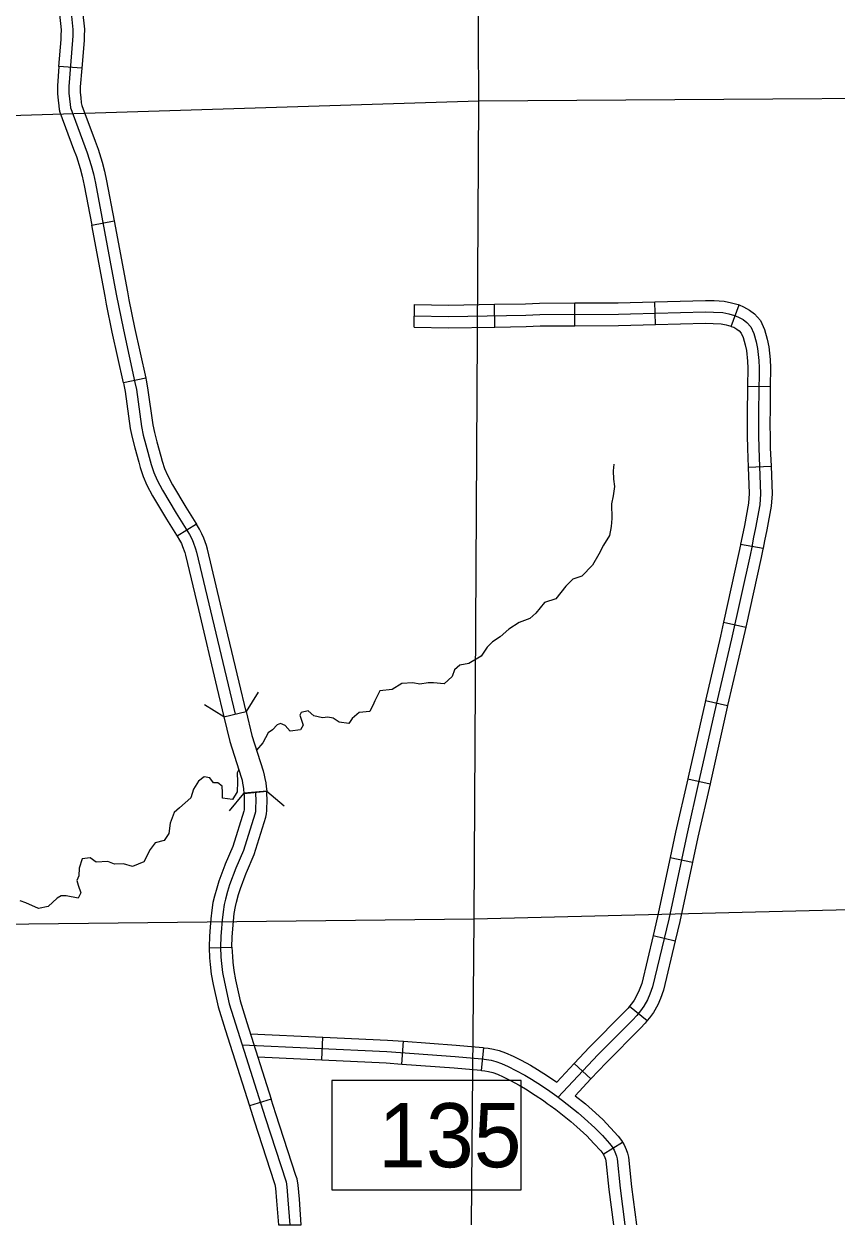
# Model space of a CAD drawing. Extents: x -492261 to -432772, y 1441225 to 1452922.
# Drawn here: x -458029.5 to -457876.9, y 1450742 to 1450967.5 of the extents above; entities that cross this region are included whole.
import ezdxf

# ---------------------------------------------------------------- set-up
doc = ezdxf.new("R2010")
doc.units = 0
doc.layers.add('Default', color=7, linetype='Continuous')

msp = doc.modelspace()

# ---------------------------------------------------------------- linework, layer by layer
at = {"layer": 'Default'}
for p, q in [((-458018.7, 1450959.21), (-458022.97, 1450959.56)), ((-458016.83, 1450929.76), (-458012.62, 1450930.54)), ((-458012.62, 1450930.54), (-458012.62, 1450930.54)), ((-457956.3, 1450910.57), (-457956.23, 1450914.86)), ((-457941.14, 1450910.61), (-457941.22, 1450914.89)), ((-457926.09, 1450910.86), (-457926.11, 1450915.15)), ((-457910.96, 1450911.08), (-457911.07, 1450915.37)), ((-457896.77, 1450910.75), (-457895.24, 1450914.76)), ((-458006.68, 1450901.04), (-458010.87, 1450900.11)), ((-457893.69, 1450899.49), (-457889.4, 1450899.43)), ((-457893.56, 1450884.3), (-457889.27, 1450884.46)), ((-457997.13, 1450873.6), (-458000.79, 1450871.36)), ((-457894.97, 1450869.82), (-457890.75, 1450869.06)), ((-457898.19, 1450855.17), (-457894.01, 1450854.24)), ((-457901.59, 1450840.5), (-457897.41, 1450839.52)), ((-457991.99, 1450837.4), (-457987.82, 1450838.39)), ((-457904.9, 1450825.77), (-457900.72, 1450824.82)), ((-457988.23, 1450823.04), (-457983.96, 1450823.45)), ((-457988.23, 1450823.06), (-457983.96, 1450823.44)), ((-457983.96, 1450823.44), (-457988.23, 1450823.06)), ((-457908.19, 1450811.02), (-457904, 1450810.12)), ((-457911.41, 1450796.33), (-457907.24, 1450795.34)), ((-457994.77, 1450794.02), (-457990.49, 1450794.18)), ((-457915.82, 1450783.06), (-457912.5, 1450780.35)), ((-457973.63, 1450772.97), (-457973.43, 1450777.25)), ((-457958.62, 1450772.2), (-457958.31, 1450776.48)), ((-457943.65, 1450771.01), (-457943.2, 1450775.27)), ((-457926.21, 1450772.33), (-457923.08, 1450769.4)), ((-457983.13, 1450765.63), (-457987.21, 1450764.33)), ((-457982.24, 1450762.82), (-457983.13, 1450765.63)), ((-457983.13, 1450765.63), (-457983.13, 1450765.63)), ((-457987.21, 1450764.33), (-457987.21, 1450764.33)), ((-457987.21, 1450764.33), (-457986.32, 1450761.51)), ((-457986.32, 1450761.51), (-457982.54, 1450749.97)), ((-457978.47, 1450751.3), (-457982.24, 1450762.82)), ((-457920.78, 1450755.28), (-457917.13, 1450757.52)), ((-457982.54, 1450749.97), (-457982.42, 1450749.58)), ((-457982.42, 1450749.58), (-457982.3, 1450748.88)), ((-457978.25, 1450750.62), (-457978.47, 1450751.3)), ((-457978.04, 1450749.43), (-457978.25, 1450750.62)), ((-457982.3, 1450748.88), (-457982.1, 1450746.5)), ((-457977.83, 1450746.83), (-457978.04, 1450749.43)), ((-457982.1, 1450746.5), (-457981.77, 1450741.98)), ((-457977.47, 1450741.98), (-457977.83, 1450746.83)), ((-457981.77, 1450741.98), (-457977.47, 1450741.98))]:
    msp.add_line(p, q, dxfattribs=at)
for points in [[(-457945.49, 1450741.98), (-457945.04, 1450799.46), (-457944.16, 1450953.01), (-457944.73, 1451070.81)], [(-458026.72, 1450989.72), (-458022.89, 1450979.69), (-458022.15, 1450977.26), (-458021.56, 1450974.82), (-458021.04, 1450972.2), (-458020.68, 1450969.62), (-458020.35, 1450966.5), (-458020.4, 1450965.3), (-458020.41, 1450964.52), (-458021.13, 1450955.82), (-458021.13, 1450954.56), (-458021.02, 1450953.47), (-458020.9, 1450952.44), (-458020.81, 1450951.83), (-458020.79, 1450951.74), (-458020.78, 1450951.67), (-458020.77, 1450951.64)], [(-458022.97, 1450959.56), (-458022.55, 1450964.62), (-458022.54, 1450965.36), (-458022.5, 1450966.44), (-458022.81, 1450969.36), (-458023.15, 1450971.85), (-458023.57, 1450973.95)], [(-458019.37, 1450974.79), (-458018.92, 1450972.56), (-458018.56, 1450969.88), (-458018.2, 1450966.57), (-458018.26, 1450965.24), (-458018.27, 1450964.42), (-458018.7, 1450959.21)], [(-458022.97, 1450959.56), (-458023.28, 1450955.9), (-458023.27, 1450954.44), (-458023.15, 1450953.24), (-458023.03, 1450952.16), (-458022.92, 1450951.47), (-458022.89, 1450951.29), (-458022.86, 1450951.14), (-458022.81, 1450950.99), (-458020.22, 1450944.05)], [(-458018.7, 1450959.21), (-458018.99, 1450955.73), (-458018.99, 1450954.67), (-458018.89, 1450953.7), (-458018.78, 1450952.72), (-458018.71, 1450952.24), (-458016.2, 1450945.55)], [(-457630.98, 1450955.82), (-457663.27, 1450955.51), (-457815.25, 1450953.91), (-457944.16, 1450953.01)], [(-457944.16, 1450953.01), (-458096.23, 1450948.31), (-458246.26, 1450948.79), (-458397.16, 1450949.72), (-458547.12, 1450949.17), (-458698.3, 1450950.04), (-458721.58, 1450950.06)], [(-458020.77, 1450951.64), (-458017.67, 1450943.34), (-458016.91, 1450940.97), (-458016.51, 1450939.42), (-458016.13, 1450937.65), (-458012.23, 1450916.8), (-458010.87, 1450910.09), (-458008.7, 1450900.22), (-458008.44, 1450898.88), (-458007.47, 1450891.91), (-458007.15, 1450890.34), (-458006.68, 1450888.51), (-458005.67, 1450884.83), (-458005.18, 1450883.3), (-458004.55, 1450881.88), (-458003.53, 1450879.96), (-458000.97, 1450875.69), (-457999.07, 1450872.66), (-457998.45, 1450871.64), (-457998.05, 1450870.85), (-457997.76, 1450870.2), (-457997.32, 1450868.95), (-457997.14, 1450868.35), (-457989.91, 1450837.9)], [(-458020.22, 1450944.05), (-458019.69, 1450942.64), (-458018.97, 1450940.38), (-458018.6, 1450938.93), (-458018.23, 1450937.22), (-458016.83, 1450929.76)], [(-458016.2, 1450945.55), (-458015.64, 1450944.04), (-458014.85, 1450941.57), (-458014.43, 1450939.91), (-458014.03, 1450938.07), (-458012.62, 1450930.54)], [(-458012.62, 1450930.54), (-458010.13, 1450917.21), (-458009.83, 1450915.75)], [(-458014.03, 1450914.9), (-458014.33, 1450916.39), (-458016.83, 1450929.76)], [(-458010.87, 1450900.11), (-458012.97, 1450909.65), (-458014.03, 1450914.9)], [(-458009.83, 1450915.75), (-458008.77, 1450910.54), (-458006.68, 1450901.04)], [(-457956.23, 1450914.86), (-457949.85, 1450914.75), (-457941.22, 1450914.89)], [(-457941.22, 1450914.89), (-457935.36, 1450914.99), (-457932.75, 1450915.11), (-457926.11, 1450915.15)], [(-457926.11, 1450915.15), (-457917.97, 1450915.19), (-457915.7, 1450915.24), (-457911.07, 1450915.37)], [(-457911.07, 1450915.37), (-457901.58, 1450915.62), (-457899.94, 1450915.58), (-457898.07, 1450915.45), (-457896.69, 1450915.19), (-457895.46, 1450914.84), (-457895.24, 1450914.76)], [(-457895.24, 1450914.76), (-457894.42, 1450914.44), (-457893.34, 1450913.81), (-457892.36, 1450913.08), (-457891.26, 1450911.84), (-457890.48, 1450910.13), (-457889.97, 1450908.33), (-457889.66, 1450906.91), (-457889.42, 1450904.52), (-457889.35, 1450902.96), (-457889.4, 1450899.43)], [(-457956.26, 1450912.72), (-457949.85, 1450912.61), (-457935.3, 1450912.85), (-457932.69, 1450912.97), (-457917.93, 1450913.05), (-457915.65, 1450913.1), (-457901.58, 1450913.48), (-457900.04, 1450913.44), (-457898.34, 1450913.32), (-457897.19, 1450913.1), (-457896.14, 1450912.8), (-457895.35, 1450912.5), (-457894.52, 1450912.02), (-457893.81, 1450911.49), (-457893.08, 1450910.66), (-457892.5, 1450909.39), (-457892.05, 1450907.81), (-457891.78, 1450906.57), (-457891.56, 1450904.36), (-457891.49, 1450902.93), (-457891.57, 1450897.68), (-457891.59, 1450895.85), (-457891.61, 1450891.95), (-457891.6, 1450890.31), (-457891.54, 1450887.88), (-457891.23, 1450879.31), (-457891.38, 1450877.25), (-457892.17, 1450872.93), (-457892.6, 1450870.85), (-457892.88, 1450869.3), (-457893.19, 1450867.8), (-457896.69, 1450852.07), (-457899.57, 1450839.7), (-457902.74, 1450825.64), (-457905.1, 1450815.26), (-457908.48, 1450799.42), (-457911.5, 1450786.71), (-457912.01, 1450785.3), (-457912.46, 1450784.28), (-457913.16, 1450783.06), (-457913.77, 1450782.18), (-457914.49, 1450781.31), (-457915.3, 1450780.46), (-457921.78, 1450773.91), (-457929.23, 1450765.98)], [(-457956.3, 1450910.57), (-457949.85, 1450910.46), (-457941.14, 1450910.61)], [(-457941.14, 1450910.61), (-457935.23, 1450910.71), (-457932.64, 1450910.83), (-457926.09, 1450910.86)], [(-457926.09, 1450910.86), (-457917.9, 1450910.91), (-457915.59, 1450910.96), (-457910.96, 1450911.08)], [(-457910.96, 1450911.08), (-457901.58, 1450911.34), (-457900.14, 1450911.3), (-457898.62, 1450911.2), (-457897.68, 1450911.02), (-457896.81, 1450910.77), (-457896.77, 1450910.75)], [(-457896.77, 1450910.75), (-457896.28, 1450910.57), (-457895.71, 1450910.23), (-457895.26, 1450909.9), (-457894.89, 1450909.48), (-457894.51, 1450908.65), (-457894.13, 1450907.3), (-457893.9, 1450906.24), (-457893.7, 1450904.2), (-457893.64, 1450902.9), (-457893.69, 1450899.49)], [(-458006.68, 1450901.04), (-458006.6, 1450900.66), (-458006.32, 1450899.23), (-458005.36, 1450892.27), (-458005.06, 1450890.82), (-458004.61, 1450889.06), (-458003.86, 1450886.35)], [(-458010.87, 1450900.11), (-458010.79, 1450899.79), (-458010.55, 1450898.53), (-458009.59, 1450891.54), (-458009.24, 1450889.85), (-458008.75, 1450887.95), (-458007.99, 1450885.21)], [(-457893.69, 1450899.49), (-457893.71, 1450897.71), (-457893.73, 1450895.86), (-457893.75, 1450891.95), (-457893.74, 1450890.28), (-457893.68, 1450887.81), (-457893.56, 1450884.3)], [(-457889.4, 1450899.43), (-457889.43, 1450897.66), (-457889.44, 1450895.83), (-457889.47, 1450891.95), (-457889.46, 1450890.34), (-457889.4, 1450887.94), (-457889.27, 1450884.46)], [(-458007.99, 1450885.21), (-458007.72, 1450884.22), (-458007.18, 1450882.53), (-458006.48, 1450880.95), (-458005.4, 1450878.9), (-458002.8, 1450874.56), (-458000.89, 1450871.53), (-458000.79, 1450871.36)], [(-458003.86, 1450886.35), (-458003.61, 1450885.44), (-458003.17, 1450884.06), (-458002.62, 1450882.82), (-458001.66, 1450881.01), (-457999.15, 1450876.81), (-457997.25, 1450873.79), (-457997.13, 1450873.6)], [(-457918.77, 1450884.88), (-457918.91, 1450883.61), (-457918.87, 1450882.06), (-457918.67, 1450880.66), (-457918.94, 1450878.94), (-457919.25, 1450877.41), (-457919.16, 1450874.63), (-457919.29, 1450873.14), (-457919.62, 1450871.44), (-457920.73, 1450869.64), (-457921.63, 1450867.98), (-457922.81, 1450865.92), (-457924.8, 1450863.84), (-457926.47, 1450863.26), (-457927.79, 1450861.93), (-457929.7, 1450859.57), (-457931.8, 1450858.86), (-457933.42, 1450856.9), (-457934.54, 1450855.85), (-457936.58, 1450855.14), (-457938.47, 1450853.89), (-457940.15, 1450852.45), (-457941.56, 1450851.5), (-457942.54, 1450850.5), (-457943.7, 1450848.81), (-457946.04, 1450847.44), (-457947.72, 1450847.09), (-457948.73, 1450846.23), (-457949.16, 1450844.96), (-457950.62, 1450843.64), (-457952.62, 1450843.82), (-457953.65, 1450843.8), (-457955.22, 1450843.53), (-457956.51, 1450843.79), (-457958.6, 1450843.66), (-457960.43, 1450842.52), (-457962.74, 1450842.3), (-457963.64, 1450840.39), (-457963.83, 1450839.95), (-457964.63, 1450838.39), (-457966.6, 1450838.23), (-457967.92, 1450837.08), (-457968.55, 1450836.15), (-457970.39, 1450836.39), (-457971.49, 1450837.14), (-457972.47, 1450837.32), (-457973.5, 1450837.24), (-457975.11, 1450837.6), (-457976.19, 1450838.52), (-457977.47, 1450838.24), (-457977.74, 1450837.71), (-457977.13, 1450835.86), (-457977.59, 1450834.94), (-457979.56, 1450834.75), (-457980.5, 1450835.76), (-457981.4, 1450836.17), (-457982.02, 1450835.9), (-457982.86, 1450834.99), (-457983.7, 1450834.42), (-457984.69, 1450832.51), (-457985.87, 1450831.12)], [(-457893.56, 1450884.3), (-457893.37, 1450879.35), (-457893.51, 1450877.52), (-457894.27, 1450873.34), (-457894.71, 1450871.26), (-457894.97, 1450869.82)], [(-457889.27, 1450884.46), (-457889.08, 1450879.27), (-457889.25, 1450876.97), (-457890.06, 1450872.51), (-457890.5, 1450870.44), (-457890.75, 1450869.06)], [(-457992.62, 1450858.58), (-457995.07, 1450868.91), (-457995.29, 1450869.62), (-457995.77, 1450870.99), (-457996.12, 1450871.76), (-457996.57, 1450872.68), (-457997.13, 1450873.6)], [(-458000.79, 1450871.36), (-458000.32, 1450870.61), (-457999.99, 1450869.94), (-457999.75, 1450869.4), (-457999.36, 1450868.28), (-457999.21, 1450867.78), (-457996.79, 1450857.59)], [(-457894.97, 1450869.82), (-457894.99, 1450869.7), (-457895.29, 1450868.25), (-457898.19, 1450855.17)], [(-457890.75, 1450869.06), (-457890.78, 1450868.89), (-457891.1, 1450867.35), (-457894.01, 1450854.24)], [(-457989.13, 1450843.9), (-457992.62, 1450858.58)], [(-457996.79, 1450857.59), (-457993.3, 1450842.91)], [(-457898.19, 1450855.17), (-457898.78, 1450852.54), (-457901.59, 1450840.5)], [(-457894.01, 1450854.24), (-457894.6, 1450851.59), (-457897.41, 1450839.52)], [(-457993.3, 1450842.91), (-457991.99, 1450837.4)], [(-457987.82, 1450838.39), (-457989.13, 1450843.9)], [(-457985.58, 1450842.04), (-457987.82, 1450838.39)], [(-457901.59, 1450840.5), (-457901.66, 1450840.18), (-457904.83, 1450826.11), (-457904.9, 1450825.77)], [(-457991.99, 1450837.4), (-457995.64, 1450839.65)], [(-457987.82, 1450838.39), (-457986.76, 1450833.91), (-457984.64, 1450827.3), (-457984.43, 1450826.48), (-457984.29, 1450825.81), (-457984.14, 1450825), (-457984.05, 1450824.35), (-457983.96, 1450823.45)], [(-457897.41, 1450839.52), (-457897.49, 1450839.22), (-457900.65, 1450825.17), (-457900.72, 1450824.82)], [(-457991.99, 1450837.4), (-457990.89, 1450832.76), (-457988.76, 1450826.11), (-457988.6, 1450825.51), (-457988.5, 1450824.98), (-457988.37, 1450824.32), (-457988.31, 1450823.86), (-457988.23, 1450823.04)], [(-457989.21, 1450827.51), (-457989.5, 1450826.87), (-457989.47, 1450825.18), (-457989.51, 1450823.34), (-457990.39, 1450821.89), (-457992.26, 1450822.16), (-457992.28, 1450823.19), (-457992.31, 1450824.37), (-457993.12, 1450825.01), (-457993.98, 1450824.99), (-457994.63, 1450825.97), (-457995.7, 1450826.15), (-457996.79, 1450825.32), (-457997.73, 1450823.81), (-457998.21, 1450822.17), (-458000.37, 1450820.31), (-458001.32, 1450819.46), (-458002.07, 1450817.46), (-458002.37, 1450815.48), (-458003.23, 1450814.2), (-458004.91, 1450813.76), (-458005.88, 1450812.5), (-458007.03, 1450810.21), (-458009.15, 1450809.33), (-458010.88, 1450809.81), (-458012.56, 1450809.74), (-458013.78, 1450810.26), (-458015.98, 1450810.12), (-458017.14, 1450810.9), (-458018.62, 1450810.72), (-458019.18, 1450808.99), (-458019.24, 1450807.58), (-458019.62, 1450806.65), (-458019.4, 1450805.8), (-458018.88, 1450804.35), (-458019.34, 1450803.36), (-458021.64, 1450803.77), (-458022.58, 1450803.78), (-458023.34, 1450803.33)], [(-457904.9, 1450825.77), (-457907.19, 1450815.72), (-457908.19, 1450811.02)], [(-457900.72, 1450824.82), (-457903, 1450814.8), (-457904, 1450810.12)], [(-457986.1, 1450823.25), (-457986.06, 1450822.78), (-457986.03, 1450821.95), (-457986.06, 1450819.97), (-457986.1, 1450819.58), (-457986.21, 1450819.11), (-457988.34, 1450812.3), (-457989.77, 1450808.97), (-457990.93, 1450805.88), (-457991.3, 1450804.63), (-457991.73, 1450803.16), (-457991.95, 1450802.16), (-457992.17, 1450800.78), (-457992.35, 1450799.25), (-457992.48, 1450797.75), (-457992.57, 1450796.13), (-457992.63, 1450794.2), (-457992.56, 1450792.28), (-457992.48, 1450791.1), (-457992.26, 1450789.42), (-457991.92, 1450787.58), (-457991.04, 1450783.51), (-457984.28, 1450762.16), (-457980.33, 1450750.1), (-457980.17, 1450749.16), (-457979.97, 1450746.67), (-457979.62, 1450741.98)], [(-457988.23, 1450823.06), (-457988.2, 1450822.64), (-457988.17, 1450821.93), (-457988.2, 1450820.11), (-457988.22, 1450819.94), (-457988.28, 1450819.68), (-457990.35, 1450813.05), (-457991.76, 1450809.77), (-457991.84, 1450809.56)], [(-457990.96, 1450819.74), (-457988.23, 1450823.04)], [(-457987.83, 1450808.06), (-457987.79, 1450808.17), (-457986.32, 1450811.55), (-457984.14, 1450818.55), (-457983.99, 1450819.21), (-457983.92, 1450819.83), (-457983.88, 1450821.97), (-457983.92, 1450822.91), (-457983.96, 1450823.44)], [(-457983.96, 1450823.45), (-457980.66, 1450820.72)], [(-457908.19, 1450811.02), (-457910.57, 1450799.89), (-457911.41, 1450796.33)], [(-457991.84, 1450809.56), (-457992.96, 1450806.56), (-457993.36, 1450805.24), (-457993.8, 1450803.7), (-457994.06, 1450802.57), (-457994.29, 1450801.08), (-457994.48, 1450799.46), (-457994.61, 1450797.9), (-457994.71, 1450796.22), (-457994.78, 1450794.19), (-457994.77, 1450794.02)], [(-457904, 1450810.12), (-457906.38, 1450798.95), (-457907.24, 1450795.34)], [(-457990.49, 1450794.18), (-457990.49, 1450794.2), (-457990.43, 1450796.03), (-457990.34, 1450797.6), (-457990.22, 1450799.03), (-457990.05, 1450800.49), (-457989.85, 1450801.76), (-457989.65, 1450802.63), (-457989.25, 1450804.03), (-457988.9, 1450805.19), (-457987.83, 1450808.06)], [(-457945.04, 1450799.46), (-457811.61, 1450802.77), (-457660.51, 1450803.37), (-457630.98, 1450803.74)], [(-458023.34, 1450803.33), (-458025.02, 1450801.77), (-458026.79, 1450801.39), (-458029.19, 1450802.48), (-458030.23, 1450802.83)], [(-458745.84, 1450800.3), (-458699.18, 1450800.33), (-458547.83, 1450799.69), (-458398.2, 1450799.72), (-458246.15, 1450797.9), (-458095.56, 1450797.76), (-457945.04, 1450799.46)], [(-457911.41, 1450796.33), (-457913.55, 1450787.32), (-457914, 1450786.1), (-457914.38, 1450785.25), (-457914.97, 1450784.21), (-457915.48, 1450783.48), (-457915.82, 1450783.06)], [(-457907.24, 1450795.34), (-457909.44, 1450786.09), (-457910.02, 1450784.5), (-457910.54, 1450783.32), (-457911.35, 1450781.91), (-457912.07, 1450780.89), (-457912.5, 1450780.35)], [(-457994.77, 1450794.02), (-457994.7, 1450792.16), (-457994.61, 1450790.89), (-457994.38, 1450789.09), (-457994.03, 1450787.16), (-457993.11, 1450782.96), (-457991.77, 1450778.71)], [(-457990.49, 1450794.18), (-457990.42, 1450792.4), (-457990.34, 1450791.32), (-457990.14, 1450789.75), (-457989.82, 1450788), (-457988.97, 1450784.06), (-457987.68, 1450780.01)], [(-457915.82, 1450783.06), (-457916.1, 1450782.72), (-457916.84, 1450781.95), (-457923.33, 1450775.4), (-457926.21, 1450772.33)], [(-457987.68, 1450780.01), (-457983.13, 1450765.63)], [(-457912.5, 1450780.35), (-457912.88, 1450779.89), (-457913.76, 1450778.96), (-457920.24, 1450772.43), (-457923.08, 1450769.4)], [(-457991.77, 1450778.71), (-457987.21, 1450764.33)], [(-457987.01, 1450777.88), (-457973.43, 1450777.25)], [(-457973.43, 1450777.25), (-457961.27, 1450776.7), (-457958.31, 1450776.48)], [(-457988.6, 1450775.81), (-457961.39, 1450774.56), (-457948.58, 1450773.62), (-457943.57, 1450773.16), (-457942.68, 1450773.06), (-457941.82, 1450772.91), (-457940.92, 1450772.67), (-457939.89, 1450772.33), (-457938.6, 1450771.76), (-457937.2, 1450771.02), (-457935.52, 1450770.1), (-457934.27, 1450769.36), (-457932.38, 1450768.17), (-457930.8, 1450767.11), (-457929.48, 1450766.16), (-457928.4, 1450765.36), (-457925.48, 1450763.06), (-457924.28, 1450762), (-457922.37, 1450760.22), (-457920.94, 1450758.77), (-457919.58, 1450757.25), (-457919.1, 1450756.63), (-457918.73, 1450756.04), (-457918.46, 1450755.38), (-457918.29, 1450754.91), (-457918.18, 1450754.39), (-457917.59, 1450748.87), (-457916.7, 1450741.98)], [(-457958.31, 1450776.48), (-457948.41, 1450775.75), (-457943.36, 1450775.29), (-457943.2, 1450775.27)], [(-457943.2, 1450775.27), (-457942.37, 1450775.19), (-457941.36, 1450775), (-457940.32, 1450774.73), (-457939.12, 1450774.33), (-457937.66, 1450773.69), (-457936.18, 1450772.91), (-457934.45, 1450771.96), (-457933.14, 1450771.18), (-457931.22, 1450769.96), (-457929.5, 1450768.82)], [(-457985.63, 1450773.53), (-457973.63, 1450772.97)], [(-457973.63, 1450772.97), (-457961.52, 1450772.42), (-457958.62, 1450772.2)], [(-457958.62, 1450772.2), (-457948.76, 1450771.48), (-457943.78, 1450771.03), (-457943.65, 1450771.01)], [(-457926.21, 1450772.33), (-457929.5, 1450768.82)], [(-457943.65, 1450771.01), (-457942.98, 1450770.94), (-457942.29, 1450770.81), (-457941.53, 1450770.62), (-457940.66, 1450770.33), (-457939.54, 1450769.83), (-457938.21, 1450769.13), (-457936.58, 1450768.24), (-457935.39, 1450767.53), (-457933.55, 1450766.37), (-457932.02, 1450765.35), (-457931.28, 1450764.82)], [(-457971.75, 1450748.57), (-457936.18, 1450748.57), (-457936.18, 1450769.11), (-457971.75, 1450769.11), (-457971.75, 1450748.57)], [(-457923.08, 1450769.4), (-457926.05, 1450766.23)], [(-457926.05, 1450766.23), (-457924.1, 1450764.7), (-457922.84, 1450763.58), (-457920.88, 1450761.76), (-457919.38, 1450760.24), (-457917.94, 1450758.63), (-457917.34, 1450757.85), (-457917.13, 1450757.52)], [(-457931.28, 1450764.82), (-457930.75, 1450764.43), (-457929.7, 1450763.66), (-457926.85, 1450761.41), (-457925.72, 1450760.41), (-457923.86, 1450758.69), (-457922.51, 1450757.31), (-457921.23, 1450755.88), (-457920.86, 1450755.41), (-457920.78, 1450755.28)], [(-457917.13, 1450757.52), (-457916.82, 1450757.02), (-457916.46, 1450756.15), (-457916.23, 1450755.49), (-457916.06, 1450754.73), (-457915.47, 1450749.12), (-457914.54, 1450741.98)], [(-457920.78, 1450755.28), (-457920.65, 1450755.06), (-457920.46, 1450754.62), (-457920.36, 1450754.32), (-457920.3, 1450754.04), (-457919.72, 1450748.62), (-457918.86, 1450741.98)]]:
    msp.add_lwpolyline(points, dxfattribs=at)
msp.add_lwpolyline([(-457971.75, 1450748.57), (-457936.18, 1450748.57), (-457936.18, 1450769.11), (-457971.75, 1450769.11)], close=True, dxfattribs=at)

# ---------------------------------------------------------------- texts
msp.add_text('135', height=12.057, dxfattribs=at).set_placement((-457963.02, 1450752.81))

doc.saveas('drawing.dxf')
